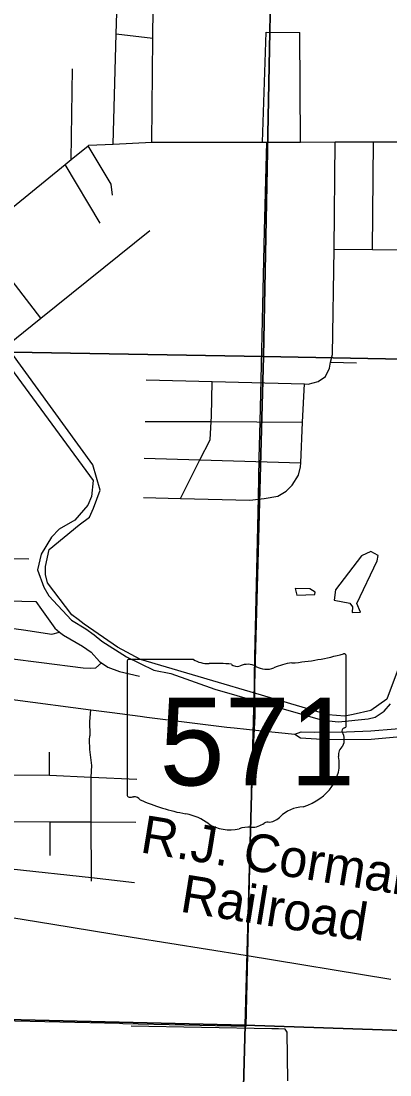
# Model space of a CAD drawing. Extents: x 0 to 68.9, y -26.1 to 22.
# Drawn here: x 5.914 to 6.469, y 16.802 to 18.387 of the extents above; entities that cross this region are included whole.
import ezdxf

# ---------------------------------------------------------------- set-up
doc = ezdxf.new("R2010")
doc.units = 0
for name, color, linetype in [('GM_X_City_Street', 7, 'Continuous'), ('GM_X_Corporation', 7, 'Continuous'), ('GM_X_County_Road', 7, 'Continuous'), ('GM_X_Major_River', 7, 'Continuous'), ('GM_X_Minor_Lake', 7, 'Continuous'), ('GM_X_Rail_Line', 7, 'Continuous'), ('GM_X_Rail_Line_Text', 7, 'Continuous'), ('GM_X_State_Location', 7, 'Continuous'), ('GM_X_State_Route', 7, 'Continuous'), ('GM_X_State_Shield', 7, 'Continuous'), ('GM_X_Township_Road', 7, 'Continuous')]:
    doc.layers.add(name, color=color, linetype=linetype)

msp = doc.modelspace()

# ---------------------------------------------------------------- linework, layer by layer
at = {"layer": 'GM_X_City_Street'}
for p, q in [((6.0572, 18.3679), (6.1126, 18.3614)), ((6.2776, 18.2051), (6.2831, 18.3706)), ((6.2831, 18.3706), (6.3333, 18.3701)), ((6.3343, 18.2052), (6.3333, 18.3701)), ((5.9894, 18.1787), (5.9915, 18.3154)), ((6.4427, 18.0436), (6.4444, 18.2054)), ((6.033, 18.0832), (5.9805, 18.1715)), ((6.3799, 17.874), (6.419, 17.873)), ((5.9571, 17.2529), (5.9568, 17.2876)), ((5.9577, 17.1325), (5.9581, 17.1832))]:
    msp.add_line(p, q, dxfattribs=at)
for points in [[(6.0526, 18.202), (6.0572, 18.3679), (6.059, 18.4313)], [(6.0515, 18.1253), (6.0496, 18.142), (6.0152, 18.1996)], [(6.1022, 17.8474), (6.2017, 17.8449), (6.3403, 17.8414), (6.346, 17.8412), (6.361, 17.8453), (6.3723, 17.8525), (6.378, 17.8652), (6.3799, 17.874), (6.3825, 17.8856), (6.3852, 18.0439), (6.3868, 18.2053)], [(6.3852, 18.0439), (6.4427, 18.0436), (6.5033, 18.0432), (6.5291, 18.043), (6.5453, 18.047), (6.5562, 18.0558), (6.5615, 18.0651), (6.5632, 18.2056)], [(5.9439, 17.9405), (5.8842, 18.0179), (5.8484, 18.0644)], [(6.1539, 17.6694), (6.1833, 17.7272), (6.1988, 17.7576), (6.2003, 17.7847), (6.2007, 17.7925), (6.2017, 17.8449)], [(6.0982, 17.6708), (6.1539, 17.6694), (6.2582, 17.6667), (6.28, 17.669), (6.3003, 17.6725), (6.3131, 17.6801), (6.3218, 17.6893), (6.3314, 17.7042), (6.3345, 17.717), (6.3348, 17.7227), (6.3376, 17.7841), (6.3403, 17.8414)], [(6.1007, 17.7851), (6.2003, 17.7847), (6.3376, 17.7841)], [(6.0995, 17.7297), (6.1833, 17.7272), (6.3348, 17.7227)], [(5.6333, 17.5825), (5.6915, 17.5817), (5.7342, 17.5811), (5.7962, 17.5803), (5.8048, 17.5801), (5.9259, 17.5785)], [(5.6315, 17.5213), (5.693, 17.5199), (5.794, 17.5177), (5.7956, 17.5176), (5.8509, 17.5164), (5.9362, 17.5144)], [(5.9362, 17.5144), (5.945, 17.5025), (5.955, 17.4882), (5.965, 17.4743), (5.972, 17.4684), (5.9777, 17.4637), (6.0066, 17.4471), (6.0197, 17.4381), (6.0323, 17.4241), (6.0351, 17.4222), (6.0447, 17.4155), (6.0621, 17.409), (6.0924, 17.4021)], [(5.851, 17.4807), (5.918, 17.4715), (5.9602, 17.4653), (5.972, 17.4684)], [(5.8511, 17.4343), (5.897, 17.4285), (5.9447, 17.4224), (6.0074, 17.4144), (6.0192, 17.4138), (6.0268, 17.4143), (6.0351, 17.4222)], [(6.0177, 17.3116), (6.018, 17.3135), (6.0178, 17.3337), (6.0192, 17.3514)], [(6.02, 17.0936), (6.02, 17.0991), (6.0197, 17.1828), (6.0195, 17.2485), (6.0196, 17.2502), (6.0207, 17.2679), (6.0178, 17.2915), (6.0169, 17.3068), (6.0177, 17.3116)], [(5.7148, 17.255), (5.781, 17.2544), (5.8034, 17.2542), (5.8405, 17.2539), (5.9022, 17.2534), (5.9571, 17.2529), (6.0196, 17.2502), (6.0885, 17.2473)], [(5.776, 17.1845), (5.7789, 17.1844), (5.8389, 17.184), (5.89, 17.1837), (5.9007, 17.1836), (5.9581, 17.1832), (6.0197, 17.1828), (6.0868, 17.1824)], [(5.8992, 17.1122), (6.02, 17.0991), (6.085, 17.092)]]:
    msp.add_lwpolyline(points, dxfattribs=at)
at = {"layer": 'GM_X_Corporation'}
for points in [[(5.2753, 18.9061), (6.2983, 18.8857), (6.2791, 17.8826), (5.2626, 17.9001)], [(6.2983, 18.8857), (7.2954, 18.8682), (7.2743, 17.8636), (6.2791, 17.8826)], [(5.2626, 17.9001), (6.2791, 17.8826), (6.2515, 16.877), (5.2394, 16.9012)], [(6.2791, 17.8826), (7.2743, 17.8636), (7.2528, 16.8431), (6.2515, 16.877)], [(5.2394, 16.9012), (6.2515, 16.877), (6.224, 15.8733), (5.2101, 15.8972), (5.2285, 16.9015)], [(6.2515, 16.877), (7.2528, 16.8431), (7.2305, 15.8522), (6.224, 15.8733)]]:
    msp.add_lwpolyline(points, close=True, dxfattribs=at)
at = {"layer": 'GM_X_County_Road'}
for points in [[(6.1108, 18.2049), (6.2776, 18.2051), (6.3343, 18.2052), (6.3868, 18.2053), (6.3915, 18.2053), (6.3956, 18.2053)], [(6.3956, 18.2053), (6.4444, 18.2054), (6.4817, 18.2054), (6.4868, 18.2054)], [(5.8144, 17.8362), (5.8181, 17.8392), (5.9439, 17.9405), (6.1076, 18.0723)], [(6.2993, 16.8716), (6.2913, 16.8717), (6.0796, 16.8756)], [(6.3155, 16.7937), (6.3147, 16.8667), (6.3114, 16.8714), (6.3014, 16.8716), (6.2993, 16.8716)]]:
    msp.add_lwpolyline(points, dxfattribs=at)
at = {"layer": 'GM_X_Major_River'}
for points in [[(6.4876, 17.4291), (6.4643, 17.3672), (6.4404, 17.3506), (6.4136, 17.3442), (6.4014, 17.3418), (6.3763, 17.3441), (6.0939, 17.4272), (6.0592, 17.4457), (6.0092, 17.48), (5.9998, 17.4874), (5.9904, 17.4944), (5.954, 17.5425), (5.9508, 17.5547), (5.9511, 17.5669), (5.9565, 17.5926), (6.0013, 17.6294), (6.0172, 17.6409), (6.0231, 17.6548), (6.0331, 17.6816), (6.0221, 17.7198), (5.8985, 17.8899), (5.7761, 18.0456), (5.7537, 18.068), (5.7353, 18.0746)], [(5.8011, 17.9977), (6.0224, 17.6962), (6.02, 17.672), (6.0148, 17.6592), (5.995, 17.6364), (5.9715, 17.6231), (5.9599, 17.6112), (5.9442, 17.5856), (5.9388, 17.5618), (5.9486, 17.5358), (5.956, 17.5228), (5.9899, 17.4861), (6.0118, 17.4731), (6.0241, 17.4642), (6.0358, 17.4544), (6.0726, 17.431), (6.1141, 17.4112), (6.1392, 17.4062), (6.2054, 17.3826), (6.3678, 17.3359), (6.3917, 17.3332), (6.4364, 17.3377), (6.4467, 17.3406), (6.4602, 17.3494), (6.4699, 17.3603)]]:
    msp.add_lwpolyline(points, dxfattribs=at)
at = {"layer": 'GM_X_Minor_Lake'}
for points in [[(6.4514, 17.5833), (6.4404, 17.5896), (6.4262, 17.583), (6.3872, 17.5317), (6.385, 17.5165)], [(6.385, 17.5165), (6.4085, 17.5119), (6.413, 17.5065), (6.4125, 17.4978), (6.4247, 17.4983), (6.4192, 17.5114), (6.4497, 17.5754), (6.4514, 17.5833)], [(6.3488, 17.5335), (6.3267, 17.5336), (6.3292, 17.5236), (6.3562, 17.5247)], [(6.3562, 17.5247), (6.3567, 17.5285), (6.3488, 17.5335)]]:
    msp.add_lwpolyline(points, dxfattribs=at)
at = {"layer": 'GM_X_Rail_Line'}
msp.add_lwpolyline([(5.7114, 17.0697), (5.9617, 17.029), (6.0815, 17.0097), (6.2511, 16.9826), (6.4706, 16.9463)], dxfattribs=at)
at = {"layer": 'GM_X_State_Route'}
for points in [[(6.1126, 18.3687), (6.1133, 18.4302), (6.1135, 18.4456), (6.1165, 18.4491), (6.1776, 18.519), (6.2514, 18.6035)], [(6.1108, 18.2049), (6.1126, 18.3614), (6.1126, 18.3687)], [(5.8139, 18.0365), (5.831, 18.0503), (5.8402, 18.0578), (5.8484, 18.0644), (5.8556, 18.0703), (5.8713, 18.083), (5.876, 18.0868), (5.9805, 18.1715), (5.9894, 18.1787), (6.0152, 18.1996), (6.0159, 18.2002), (6.0526, 18.202), (6.1108, 18.2049)], [(5.6964, 17.3809), (5.7223, 17.3814), (5.7734, 17.3794), (5.7835, 17.3788), (5.7945, 17.378), (5.8307, 17.3759), (5.8877, 17.3689), (5.9053, 17.3662), (6.0192, 17.3514), (6.0513, 17.3473), (6.0932, 17.3417), (6.1033, 17.3404)], [(6.1033, 17.3404), (6.2236, 17.3252), (6.2346, 17.3241)], [(6.3258, 17.3148), (6.3353, 17.3183), (6.3555, 17.318), (6.4038, 17.3183), (6.4402, 17.3199), (6.4769, 17.3229), (6.5124, 17.3269), (6.5423, 17.3313), (6.6024, 17.3418)], [(6.2346, 17.3241), (6.2716, 17.3201), (6.3258, 17.3148)], [(6.3258, 17.3148), (6.3345, 17.3092), (6.3748, 17.3066), (6.4406, 17.3075), (6.5126, 17.3136), (6.6027, 17.3294), (6.6124, 17.331)]]:
    msp.add_lwpolyline(points, dxfattribs=at)
at = {"layer": 'GM_X_State_Shield'}
for p, q in [((6.4033, 17.3275), (6.4033, 17.4322)), ((6.0737, 17.4238), (6.0737, 17.2237)), ((6.1735, 17.4272), (6.0769, 17.4272)), ((6.4032, 17.3275), (6.4033, 17.3275))]:
    msp.add_line(p, q, dxfattribs=at)
for centre, major_axis, start_param, end_param in [((6.2859, 17.7), (0.3495, 0), 4.814394, 5.042369), ((6.3996, 17.4326), (0.00367, 0), 6.141152, 7.989035), ((6.0775, 17.4242), (0.00382, 0), 1.712693, 3.28349), ((6.1964, 17.4504), (0.037, 0), 4.042523, 4.731795), ((6.2087, 17.3149), (0.133, 0), 1.404758, 1.657858), ((6.2389, 17.4252), (0.0107, 0), 3.836095, 5.185415), ((6.2546, 17.4021), (0.0222, 0), 0.950623, 2.079405), ((6.2833, 17.4338), (0.0267, 0), 4.081561, 5.145723), ((6.3305, 17.3661), (0.0703, 0), 1.699011, 2.107814), ((6.4024, 17.3198), (0.00568, 0), 1.883978, 3.671073), ((6.3994, 17.3271), (0.00393, 0), 5.05454, 6.418171), ((6.3663, 17.3066), (0.0341, 0), 5.934695, 6.695948), ((6.4164, 17.2837), (0.0248, 0), 2.387724, 3.262537), ((6.3055, 17.2704), (0.0874, 0), 5.101752, 6.440018), ((6.0775, 17.2232), (0.00385, 0), 3.00124, 4.508301), ((6.0781, 17.2437), (0.0294, 0), 4.665946, 4.897461), ((6.0841, 17.2121), (0.0106, 0), 0.519207, 1.627899), ((6.2179, 17.3919), (0.2524, 0), 4.195997, 4.488961), ((6.1427, 17.1337), (0.079, 0), 0.823519, 1.323587), ((6.3423, 17.1675), (0.0479, 0), 1.647645, 2.488434), ((6.2281, 17.2111), (0.0501, 0), 4.026481, 4.996735), ((6.2607, 17.1961), (0.0267, 0), 4.691044, 5.507374), ((6.2849, 17.1767), (0.00752, 0), 1.147584, 2.315152), ((6.2817, 17.2043), (0.0282, 0), 4.937069, 5.64225), ((6.257, 17.1419), (0.0412, 0), 1.495662, 1.94098)]:
    msp.add_ellipse(centre, major_axis=major_axis, ratio=0.8, start_param=start_param, end_param=end_param, dxfattribs=at)
at = {"layer": 'GM_X_Township_Road'}
msp.add_line((5.8823, 16.8841), (6.0622, 16.88), dxfattribs=at)
for points in [[(6.266, 17.4312), (6.2712, 17.6708), (6.2724, 17.7297), (6.2737, 17.7851), (6.2752, 17.8474), (6.2806, 18.0723), (6.2838, 18.2049)], [(6.2661, 17.3417), (6.2654, 17.4021), (6.266, 17.4302), (6.266, 17.4312)], [(6.2526, 16.8756), (6.2579, 17.092), (6.2598, 17.1824), (6.2615, 17.2473), (6.2661, 17.3417)], [(6.0622, 16.88), (6.0672, 16.8799), (6.2526, 16.8756)]]:
    msp.add_lwpolyline(points, dxfattribs=at)

# ---------------------------------------------------------------- texts
at = {"layer": 'GM_X_Rail_Line_Text'}
for s, height, rotation, p in [('R.J. Corman', 0.056629, 350.7396, (6.0918, 17.1374)), ('Railroad', 0.05663, 350.8563, (6.1517, 17.0482))]:
    msp.add_text(s, height=height, rotation=rotation, dxfattribs=at).set_placement(p)
at = {"layer": 'GM_X_State_Location'}
for s in ['s', 'r']:
    msp.add_text(s, height=0.000189, dxfattribs=at).set_placement((6.2348, 17.3104))
msp.add_text('571', height=0.000189, rotation=0, dxfattribs=at).set_placement((6.1679, 17.2966))
at = {"layer": 'GM_X_State_Shield'}
msp.add_text('571', height=0.13184, dxfattribs=at).set_placement((6.1223, 17.2378))

doc.saveas('drawing.dxf')
